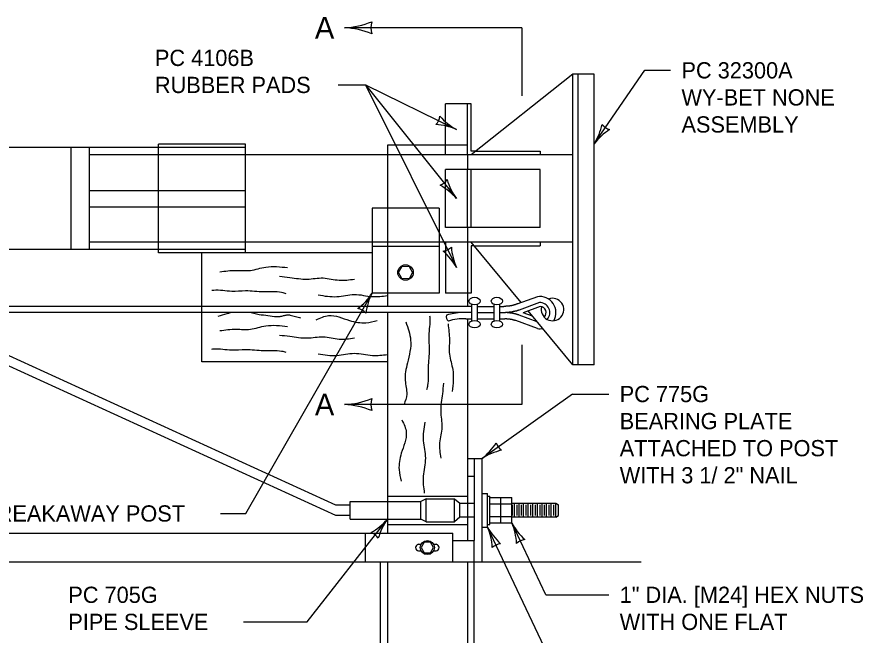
# Model space of a CAD drawing. Extents: x 49991.4 to 50021, y 49987.6 to 50011.4.
# Drawn here: x 50007.796 to 50010.92, y 49991.023 to 49993.307 of the extents above; entities that cross this region are included whole.
import ezdxf

# ---------------------------------------------------------------- set-up
doc = ezdxf.new("R2010")
doc.units = 0
for name, color, linetype in [('Level 1', 7, 'Continuous'), ('Level 2', 7, 'Continuous'), ('Level 3', 7, 'Continuous'), ('Level 4', 7, 'Continuous'), ('Level 6', 7, 'Continuous')]:
    doc.layers.add(name, color=color, linetype=linetype)

msp = doc.modelspace()

# ---------------------------------------------------------------- linework, layer by layer
at = {"layer": 'Level 1'}
for p, q in [((50009.8485, 49993.0962), (50009.4728, 49992.7977)), ((50009.8485, 49992.0223), (50009.8485, 49993.0962)), ((50009.9278, 49993.0962), (50009.8485, 49993.0962)), ((50009.8688, 49992.0223), (50009.8688, 49993.0962)), ((50009.9278, 49992.0223), (50009.9278, 49993.0962)), ((50009.3788, 49992.7977), (50009.3788, 49992.9857)), ((50009.4728, 49992.9857), (50009.3788, 49992.9857)), ((50009.4593, 49992.7977), (50009.4593, 49992.9857)), ((50009.4728, 49992.8112), (50009.4728, 49992.9857)), ((50008.3182, 49992.4355), (50008.3182, 49992.8375)), ((50008.6405, 49992.8375), (50008.3182, 49992.8375)), ((50008.6405, 49992.4355), (50008.6405, 49992.8375)), ((50009.3788, 49992.8334), (50009.1638, 49992.8334)), ((50009.1638, 49992.8334), (50009.1638, 49992.7977)), ((50008.3182, 49992.8247), (50004.6559, 49992.8247)), ((50009.8485, 49992.7977), (50008.6405, 49992.7977)), ((50009.4898, 49992.8112), (50009.4728, 49992.8112)), ((50009.7279, 49992.7437), (50009.3788, 49992.7437)), ((50009.3788, 49992.5294), (50009.3788, 49992.7437)), ((50009.4593, 49992.5294), (50009.4593, 49992.7437)), ((50009.4728, 49992.5294), (50009.4728, 49992.7437)), ((50009.7279, 49992.5294), (50009.7279, 49992.7437)), ((50009.3546, 49992.6008), (50009.1075, 49992.6008)), ((50009.1075, 49992.6008), (50009.1075, 49992.2873)), ((50009.3546, 49992.6008), (50009.3546, 49992.2873)), ((50009.7279, 49992.5294), (50009.3788, 49992.5294)), ((50009.1075, 49992.4753), (50008.6405, 49992.4753)), ((50009.3546, 49992.459), (50009.1075, 49992.459)), ((50009.8485, 49992.4753), (50009.3546, 49992.4753)), ((50009.3788, 49992.4753), (50009.3788, 49992.2873)), ((50009.4593, 49992.4753), (50009.4593, 49992.2379)), ((50009.6579, 49992.2521), (50009.4728, 49992.4753)), ((50009.4728, 49992.4619), (50009.4728, 49992.2873)), ((50009.4839, 49992.4619), (50009.4728, 49992.4619)), ((50008.3182, 49992.4484), (50004.6559, 49992.4484)), ((50008.6405, 49992.4355), (50008.3182, 49992.4355)), ((50009.1075, 49992.4355), (50008.4793, 49992.4355)), ((50008.4793, 49992.0335), (50008.4793, 49992.4355)), ((50009.3546, 49992.2873), (50009.1075, 49992.2873)), ((50009.1638, 49992.2873), (50009.1638, 49992.2379)), ((50009.4728, 49992.2873), (50009.3788, 49992.2873)), ((50009.7178, 49992.2736), (50009.6416, 49992.2463)), ((50009.4754, 49992.2379), (50006.4958, 49992.2379)), ((50009.4754, 49992.184), (50009.4754, 49992.2458)), ((50009.4967, 49992.1839), (50009.4967, 49992.2459)), ((50009.4967, 49992.2379), (50009.5578, 49992.2379)), ((50009.5578, 49992.1839), (50009.5578, 49992.2458)), ((50009.579, 49992.184), (50009.579, 49992.2458)), ((50009.579, 49992.2379), (50009.5943, 49992.2379)), ((50009.7251, 49992.2518), (50009.6501, 49992.2242)), ((50009.7285, 49992.238), (50009.6653, 49992.2145)), ((50008.5847, 49992.215), (50006.4958, 49992.215)), ((50008.9741, 49991.4648), (50007.3336, 49992.215)), ((50008.9741, 49991.5036), (50007.4186, 49992.215)), ((50009.4754, 49992.215), (50008.5847, 49992.215)), ((50009.1638, 49992.215), (50009.1638, 49991.4003)), ((50009.4967, 49992.215), (50009.5578, 49992.215)), ((50009.579, 49992.215), (50009.6005, 49992.215)), ((50009.7169, 49992.1809), (50009.6501, 49992.2057)), ((50009.7, 49992.2013), (50009.6653, 49992.2145)), ((50009.8485, 49992.0223), (50009.6835, 49992.2213)), ((50009.4538, 49992.192), (50009.4754, 49992.192)), ((50009.4593, 49992.192), (50009.4593, 49991.3728)), ((50009.4967, 49992.192), (50009.5578, 49992.192)), ((50009.579, 49992.192), (50009.5976, 49992.192)), ((50009.7185, 49992.156), (50009.6386, 49992.1855)), ((50009.1638, 49992.0335), (50008.4793, 49992.0335)), ((50009.9278, 49992.0223), (50009.8485, 49992.0223)), ((50009.4593, 49991.6758), (50009.5135, 49991.6758)), ((50009.4845, 49991.6758), (50009.4845, 49991.3728)), ((50009.5135, 49991.2942), (50009.5135, 49991.6758)), ((50009.4593, 49991.6101), (50009.4845, 49991.6101)), ((50009.027, 49991.4515), (50009.027, 49991.5169)), ((50009.027, 49991.5169), (50009.1638, 49991.5169)), ((50009.5135, 49991.5468), (50009.5341, 49991.5468)), ((50009.5341, 49991.4226), (50009.5341, 49991.5468)), ((50009.5426, 49991.4326), (50009.5426, 49991.5368)), ((50009.5426, 49991.5313), (50009.6235, 49991.5313)), ((50009.5831, 49991.4381), (50009.5831, 49991.5313)), ((50009.6235, 49991.4381), (50009.6235, 49991.5313)), ((50009.027, 49991.5036), (50008.9741, 49991.5036)), ((50009.4593, 49991.5107), (50009.4845, 49991.5107)), ((50009.5426, 49991.5081), (50009.6235, 49991.5081)), ((50009.6235, 49991.5107), (50009.7861, 49991.5107)), ((50009.6264, 49991.4648), (50009.6264, 49991.5044)), ((50009.6338, 49991.4586), (50009.6338, 49991.5107)), ((50009.6435, 49991.4648), (50009.6435, 49991.5044)), ((50009.6508, 49991.4586), (50009.6508, 49991.5107)), ((50009.6596, 49991.4648), (50009.6596, 49991.5044)), ((50009.6669, 49991.4586), (50009.6669, 49991.5107)), ((50009.677, 49991.4648), (50009.677, 49991.5044)), ((50009.6842, 49991.4586), (50009.6842, 49991.5107)), ((50009.6939, 49991.4648), (50009.6939, 49991.5044)), ((50009.7013, 49991.4586), (50009.7013, 49991.5107)), ((50009.711, 49991.4648), (50009.711, 49991.5044)), ((50009.7185, 49991.4586), (50009.7185, 49991.5107)), ((50009.7281, 49991.4648), (50009.7281, 49991.5044)), ((50009.7354, 49991.4586), (50009.7354, 49991.5107)), ((50009.7446, 49991.4648), (50009.7446, 49991.5044)), ((50009.7518, 49991.4586), (50009.7518, 49991.5107)), ((50009.7616, 49991.4648), (50009.7616, 49991.5044)), ((50009.7691, 49991.4586), (50009.7691, 49991.5107)), ((50009.7788, 49991.4648), (50009.7788, 49991.5044)), ((50009.7861, 49991.4586), (50009.7861, 49991.5107)), ((50009.7861, 49991.5107), (50009.7959, 49991.5044)), ((50009.7959, 49991.4648), (50009.7959, 49991.5044)), ((50009.027, 49991.4648), (50008.9741, 49991.4648)), ((50009.4845, 49991.4586), (50009.4593, 49991.4586)), ((50009.5426, 49991.4612), (50009.6235, 49991.4612)), ((50009.7861, 49991.4586), (50009.6235, 49991.4586)), ((50009.7861, 49991.4586), (50009.7959, 49991.4648)), ((50009.027, 49991.4515), (50009.1638, 49991.4515)), ((50009.5135, 49991.4226), (50009.5341, 49991.4226)), ((50009.5426, 49991.4381), (50009.6235, 49991.4381)), ((50005.1777, 49991.4003), (50009.4058, 49991.4003)), ((50009.0831, 49991.2942), (50009.0831, 49991.4003)), ((50009.4058, 49991.2942), (50009.4058, 49991.4003)), ((50009.4058, 49991.3728), (50009.4845, 49991.3728)), ((50009.4845, 49991.2942), (50009.4845, 49991.3728)), ((50009.2783, 49991.359), (50009.2884, 49991.359)), ((50009.2787, 49991.335), (50009.2884, 49991.335)), ((50009.3345, 49991.335), (50009.3442, 49991.335)), ((50009.3346, 49991.359), (50009.3446, 49991.359)), ((50004.6559, 49991.2942), (50010.1006, 49991.2942))]:
    msp.add_line(p, q, dxfattribs=at)
for points in [[(50009.2183, 49992.386), (50009.244, 49992.3856), (50009.2571, 49992.3631), (50009.2438, 49992.3402), (50009.2177, 49992.3405), (50009.2046, 49992.3633)], [(50009.3231, 49991.327), (50009.3346, 49991.347), (50009.3229, 49991.3671), (50009.2999, 49991.3668), (50009.2885, 49991.3469), (50009.3001, 49991.3268)]]:
    msp.add_lwpolyline(points, close=True, dxfattribs=at)
for points in [[(50009.5341, 49991.5368), (50009.5426, 49991.5368)], [(50009.5341, 49991.4326), (50009.5426, 49991.4326)]]:
    msp.add_lwpolyline(points, dxfattribs=at)
for centre, radius in [((50009.2309, 49992.3631), 0.0287), ((50009.3115, 49991.347), 0.026)]:
    msp.add_circle(centre, radius, dxfattribs=at)
for centre, radius, start, end in [((50009.727, 49992.2149), 0.0595, 329.9229, 98.9717), ((50009.7737, 49992.2262), 0.0415, 164.899, 110.7513), ((50009.727, 49992.2149), 0.037, 317.1104, 92.9441), ((50009.727, 49992.2149), 0.0231, 314.0927, 86.4422), ((50009.3989, 49992.1983), 0.0179, 157.1023, 236.7594), ((50009.4457, 49992.0062), 0.2089, 91.5307, 107.6367), ((50009.4457, 49992.0063), 0.1859, 87.514, 107.7489), ((50009.727, 49992.2149), 0.0595, 261.7086, 279.9748), ((50009.2802, 49991.347), 0.0121, 99.104, 263.011), ((50009.3427, 49991.347), 0.0121, 276.989, 80.896)]:
    msp.add_arc(centre, radius, start, end, dxfattribs=at)
for centre in [(50009.4859, 49992.2577), (50009.5685, 49992.2577), (50009.4859, 49992.172), (50009.5685, 49992.172)]:
    msp.add_ellipse(centre, major_axis=(-0.0209, 0), ratio=0.660302, dxfattribs=at)
for points in [[(50008.5452, 49992.3657), (50008.6054, 49992.371), (50008.6581, 49992.371), (50008.7148, 49992.3833), (50008.7956, 49992.381)], [(50008.7654, 49992.349), (50008.8038, 49992.3449), (50008.8683, 49992.3386), (50008.9272, 49992.3428), (50008.9853, 49992.3347), (50009.042, 49992.3386)], [(50008.5161, 49992.2977), (50008.5228, 49992.2984), (50008.5892, 49992.2944), (50008.6401, 49992.2963), (50008.7068, 49992.2925), (50008.7733, 49992.2903), (50008.7893, 49992.2861)], [(50008.9087, 49992.2804), (50008.9775, 49992.2741), (50009.042, 49992.2821), (50009.1088, 49992.2741), (50009.1638, 49992.2776)], [(50009.644, 49992.2472), (50009.643, 49992.2468), (50009.6421, 49992.2465), (50009.6409, 49992.2462), (50009.64, 49992.2458), (50009.6393, 49992.2455), (50009.6384, 49992.2451), (50009.6374, 49992.2447), (50009.6364, 49992.2444), (50009.6355, 49992.244), (50009.6347, 49992.2437), (50009.6338, 49992.2434), (50009.6328, 49992.2432), (50009.6319, 49992.2429), (50009.631, 49992.2427), (50009.6302, 49992.2424), (50009.6293, 49992.2422), (50009.6282, 49992.242), (50009.6274, 49992.2417), (50009.6267, 49992.2415), (50009.6256, 49992.2412), (50009.6243, 49992.2407), (50009.6235, 49992.2405), (50009.6225, 49992.2403), (50009.6216, 49992.2401), (50009.6206, 49992.2399), (50009.6196, 49992.2398), (50009.6187, 49992.2397), (50009.6177, 49992.2396), (50009.6169, 49992.2396), (50009.6161, 49992.2394), (50009.615, 49992.2393), (50009.6141, 49992.2392), (50009.613, 49992.2391), (50009.6118, 49992.239), (50009.6107, 49992.239), (50009.6099, 49992.2389), (50009.609, 49992.2389), (50009.608, 49992.2388), (50009.6069, 49992.2387), (50009.6063, 49992.2386), (50009.6055, 49992.2384), (50009.6041, 49992.2383), (50009.6032, 49992.2382), (50009.602, 49992.2382), (50009.6009, 49992.2381), (50009.6002, 49992.238), (50009.5994, 49992.2379), (50009.5984, 49992.2379), (50009.5975, 49992.2379), (50009.5966, 49992.2379), (50009.5957, 49992.2379), (50009.5943, 49992.2379)], [(50008.5388, 49992.2021), (50008.5721, 49992.2115), (50008.5847, 49992.215)], [(50008.6604, 49992.215), (50008.6802, 49992.21), (50008.6903, 49992.2083), (50008.7228, 49992.2041), (50008.7553, 49992.2001), (50008.7616, 49992.2), (50008.7679, 49992.2007), (50008.7804, 49992.2037), (50008.793, 49992.2063), (50008.7993, 49992.2066), (50008.8055, 49992.2058), (50008.8247, 49992.201), (50008.8437, 49992.196)], [(50008.9006, 49992.188), (50008.9471, 49992.204), (50009.0239, 49992.1857), (50009.0846, 49992.1775), (50009.1268, 49992.1857)], [(50009.6518, 49992.2248), (50009.6509, 49992.2245), (50009.6501, 49992.2242), (50009.6488, 49992.2237), (50009.6475, 49992.2233), (50009.6466, 49992.223), (50009.6454, 49992.2226), (50009.6443, 49992.2221), (50009.644, 49992.222), (50009.6438, 49992.2218), (50009.6436, 49992.2217), (50009.6433, 49992.2215), (50009.6418, 49992.2211), (50009.6409, 49992.2208), (50009.6401, 49992.2206), (50009.6391, 49992.2203), (50009.6379, 49992.2201), (50009.6371, 49992.2201), (50009.6361, 49992.22), (50009.635, 49992.2197), (50009.634, 49992.2195), (50009.6326, 49992.2192), (50009.6319, 49992.2191), (50009.6315, 49992.2191), (50009.6312, 49992.2191), (50009.6303, 49992.2189), (50009.6293, 49992.2187), (50009.6281, 49992.2185), (50009.627, 49992.2182), (50009.6259, 49992.2178), (50009.6247, 49992.2174), (50009.6237, 49992.2171), (50009.6234, 49992.2171), (50009.6232, 49992.217), (50009.6226, 49992.217), (50009.6213, 49992.2168), (50009.6202, 49992.2167), (50009.6191, 49992.2167), (50009.6182, 49992.2167), (50009.6172, 49992.2166), (50009.6159, 49992.2164), (50009.6149, 49992.2162), (50009.614, 49992.2161), (50009.6128, 49992.2159), (50009.6117, 49992.2158), (50009.6105, 49992.2156), (50009.6102, 49992.2156), (50009.6099, 49992.2155), (50009.6097, 49992.2154), (50009.6094, 49992.2154), (50009.609, 49992.2154), (50009.6087, 49992.2154), (50009.6079, 49992.2154), (50009.6071, 49992.2153), (50009.6059, 49992.2151), (50009.6045, 49992.215), (50009.604, 49992.215), (50009.6022, 49992.215), (50009.6012, 49992.215), (50009.6005, 49992.215)], [(50009.651, 49992.2054), (50009.6506, 49992.2055), (50009.6501, 49992.2057), (50009.6487, 49992.2062), (50009.6476, 49992.2065), (50009.6468, 49992.2067), (50009.6453, 49992.2071), (50009.6445, 49992.2074), (50009.6431, 49992.2079), (50009.6421, 49992.2083), (50009.6413, 49992.2085), (50009.6401, 49992.2088), (50009.6387, 49992.2092), (50009.6377, 49992.2095), (50009.6367, 49992.2098), (50009.6358, 49992.21), (50009.6347, 49992.2103), (50009.6336, 49992.2105), (50009.6325, 49992.2108), (50009.6321, 49992.2108), (50009.6318, 49992.2108), (50009.6315, 49992.2109), (50009.6312, 49992.2109), (50009.6301, 49992.2112), (50009.6292, 49992.2114), (50009.6279, 49992.2118), (50009.6276, 49992.2118), (50009.6274, 49992.2119), (50009.6271, 49992.212), (50009.6269, 49992.2121), (50009.626, 49992.2123), (50009.6247, 49992.2126), (50009.6238, 49992.2127), (50009.6234, 49992.2128), (50009.6231, 49992.2129), (50009.6228, 49992.213), (50009.6225, 49992.213), (50009.6215, 49992.2131), (50009.6204, 49992.2132), (50009.6189, 49992.2133), (50009.6178, 49992.2133), (50009.617, 49992.2134), (50009.6157, 49992.2135), (50009.6145, 49992.2136), (50009.6134, 49992.2137), (50009.6123, 49992.2139), (50009.6113, 49992.214), (50009.6102, 49992.2141), (50009.6089, 49992.2144), (50009.6086, 49992.2144), (50009.6083, 49992.2144), (50009.6079, 49992.2145), (50009.6076, 49992.2145), (50009.6068, 49992.2147), (50009.6056, 49992.2148), (50009.6053, 49992.2148), (50009.605, 49992.2149), (50009.6044, 49992.215), (50009.604, 49992.215), (50009.6022, 49992.215), (50009.6012, 49992.215), (50009.6005, 49992.215)], [(50009.2317, 49992.1803), (50009.2499, 49992.1137), (50009.2379, 49992.0288), (50009.2297, 49991.9638), (50009.2354, 49991.9136), (50009.2256, 49991.8754)], [(50009.3198, 49992.203), (50009.3205, 49992.1963), (50009.3165, 49992.1299), (50009.3184, 49992.079), (50009.3146, 49992.0123), (50009.3124, 49991.9458), (50009.3082, 49991.9298)], [(50009.3878, 49992.1739), (50009.3931, 49992.1137), (50009.3931, 49992.061), (50009.4054, 49992.0043), (50009.4031, 49991.9235)], [(50009.6386, 49992.1855), (50009.6377, 49992.1857), (50009.6365, 49992.1859), (50009.6357, 49992.186), (50009.6348, 49992.1861), (50009.634, 49992.1863), (50009.6331, 49992.1865), (50009.6321, 49992.1867), (50009.6309, 49992.1869), (50009.63, 49992.1872), (50009.6293, 49992.1874), (50009.628, 49992.1879), (50009.6272, 49992.1881), (50009.6266, 49992.1883), (50009.6256, 49992.1886), (50009.6252, 49992.1886), (50009.6249, 49992.1887), (50009.6246, 49992.1887), (50009.6242, 49992.1888), (50009.624, 49992.1889), (50009.6238, 49992.189), (50009.6236, 49992.189), (50009.6234, 49992.1891), (50009.6225, 49992.1893), (50009.6218, 49992.1895), (50009.6206, 49992.1897), (50009.6195, 49992.19), (50009.6192, 49992.19), (50009.619, 49992.19), (50009.6184, 49992.19), (50009.6177, 49992.19), (50009.6169, 49992.1901), (50009.6156, 49992.1902), (50009.6149, 49992.1903), (50009.6141, 49992.1903), (50009.6131, 49992.1905), (50009.6126, 49992.1905), (50009.6123, 49992.1905), (50009.6121, 49992.1905), (50009.6108, 49992.1906), (50009.61, 49992.1907), (50009.6097, 49992.1907), (50009.6095, 49992.1907), (50009.6093, 49992.1907), (50009.609, 49992.1908), (50009.6082, 49992.1909), (50009.6072, 49992.191), (50009.6064, 49992.1911), (50009.6053, 49992.1913), (50009.6044, 49992.1914), (50009.6036, 49992.1915), (50009.6026, 49992.1917), (50009.6016, 49992.1917), (50009.6006, 49992.1918), (50009.5996, 49992.1918), (50009.5987, 49992.192), (50009.5976, 49992.192)], [(50008.5452, 49992.1483), (50008.6054, 49992.1536), (50008.6581, 49992.1536), (50008.7148, 49992.1659), (50008.7956, 49992.1636)], [(50008.7654, 49992.1316), (50008.8038, 49992.1275), (50008.8683, 49992.1212), (50008.9272, 49992.1254), (50008.9853, 49992.1173), (50009.042, 49992.1212)], [(50008.5161, 49992.0803), (50008.5228, 49992.081), (50008.5892, 49992.077), (50008.6401, 49992.0789), (50008.7068, 49992.0751), (50008.7733, 49992.0729), (50008.7893, 49992.0687)], [(50008.9087, 49992.063), (50008.9775, 49992.0567), (50009.042, 49992.0647), (50009.1088, 49992.0567), (50009.1638, 49992.0602)], [(50009.3711, 49991.9537), (50009.367, 49991.9153), (50009.3607, 49991.8508), (50009.3649, 49991.7919), (50009.3568, 49991.7338), (50009.3607, 49991.6771)], [(50009.2176, 49991.8185), (50009.2336, 49991.772), (50009.2153, 49991.6952), (50009.2071, 49991.6345), (50009.2153, 49991.5923)], [(50009.3025, 49991.8104), (50009.2962, 49991.7416), (50009.3042, 49991.6771), (50009.2962, 49991.6103), (50009.3002, 49991.5476)]]:
    msp.add_spline(points, degree=3, dxfattribs=at)
at = {"layer": 'Level 3'}
for p, q in [((50009.9278, 49992.8382), (50010.1145, 49993.1101)), ((50008.9824, 49993.0561), (50009.0836, 49993.0561)), ((50009.0836, 49993.0561), (50009.4191, 49992.8917)), ((50009.0836, 49993.0561), (50009.4191, 49992.6365)), ((50009.0836, 49993.0561), (50009.4191, 49992.3813)), ((50008.6417, 49991.4728), (50009.1075, 49992.2873)), ((50008.5482, 49991.4728), (50008.6417, 49991.4728))]:
    msp.add_line(p, q, dxfattribs=at)
for points in [[(50010.1145, 49993.1101), (50010.2099, 49993.1101)], [(50009.8474, 49991.9141), (50009.5135, 49991.6758)], [(50009.8474, 49991.9141), (50009.9818, 49991.9141)], [(50008.8674, 49991.0723), (50009.1638, 49991.4515)], [(50009.8418, 49990.7723), (50009.5341, 49991.4226)], [(50009.7493, 49991.1723), (50009.6235, 49991.4381)], [(50009.7493, 49991.1723), (50009.9818, 49991.1723)], [(50008.6326, 49991.0723), (50008.8674, 49991.0723)]]:
    msp.add_lwpolyline(points, dxfattribs=at)
for centre, radius, start, end in [((50008.9898, 49993.5777), 0.3107, 272.8273, 292.0772), ((50008.9929, 49992.9712), 0.2964, 67.456, 87.6395), ((50009.1761, 49993.2674), 0.073, 162.1388, 197.8612), ((50009.3039, 49992.9481), 0.0548, 316.0333, 351.7556), ((50009.525, 49993.0871), 0.2223, 221.3505, 241.534), ((50009.327, 49992.6777), 0.233, 66.7218, 85.9716), ((50009.7294, 49992.9605), 0.233, 328.3519, 347.6017), ((50010.1057, 49992.7049), 0.2223, 122.9806, 143.1641), ((50010.0003, 49992.9439), 0.0548, 217.6634, 253.3858), ((50009.339, 49992.7366), 0.0548, 290.7836, 326.506), ((50009.5983, 49992.7681), 0.2223, 196.1008, 216.2843), ((50009.2445, 49992.4822), 0.233, 41.4721, 60.722), ((50009.362, 49992.4961), 0.0548, 278.5747, 314.297), ((50009.6221, 49992.472), 0.2223, 183.8919, 204.0754), ((50009.2158, 49992.2674), 0.233, 29.2632, 48.513), ((50008.9192, 49992.4055), 0.2223, 307.6919, 327.8754), ((50009.3152, 49992.1818), 0.233, 153.0632, 172.313), ((50009.0438, 49992.176), 0.0548, 42.3747, 78.097), ((50008.9898, 49992.1855), 0.3107, 272.8273, 292.0772), ((50009.1761, 49991.8752), 0.073, 162.1388, 197.8612), ((50008.9929, 49991.579), 0.2964, 67.456, 87.6395), ((50009.3689, 49991.8585), 0.233, 308.3423, 327.5921), ((50009.6351, 49991.4897), 0.2223, 102.971, 123.1545), ((50009.6178, 49991.7503), 0.0548, 197.6538, 233.3761), ((50008.9944, 49991.5955), 0.2223, 299.4417, 319.6252), ((50009.3542, 49991.3172), 0.233, 144.813, 164.0629), ((50009.3294, 49991.3359), 0.2223, 2.7779, 22.9614), ((50009.7395, 49991.5325), 0.233, 208.1492, 227.3991), ((50009.4188, 49991.3513), 0.2223, 2.7837, 22.9672), ((50009.8289, 49991.548), 0.233, 208.155, 227.4048), ((50009.0848, 49991.3505), 0.0548, 34.1245, 69.8469), ((50009.5889, 49991.3067), 0.0548, 97.4608, 133.1831), ((50009.6783, 49991.3222), 0.0548, 97.4665, 133.1888)]:
    msp.add_arc(centre, radius, start, end, dxfattribs=at)
at = {"layer": 'Level 4'}
for p, q in [((50009.4593, 49992.8334), (50009.3788, 49992.8334)), ((50007.996, 49992.4484), (50007.996, 49992.8247)), ((50008.0639, 49992.4484), (50008.0639, 49992.8247)), ((50008.6405, 49992.7977), (50008.0639, 49992.7977)), ((50008.6405, 49992.8247), (50008.3182, 49992.8247)), ((50009.1638, 49992.7977), (50009.1638, 49992.2873)), ((50009.4593, 49992.7977), (50009.4593, 49992.7437)), ((50009.4898, 49992.8112), (50009.7279, 49992.8112)), ((50009.7279, 49992.8112), (50009.7279, 49992.7977)), ((50008.6405, 49992.6647), (50008.0639, 49992.6647)), ((50008.6405, 49992.6043), (50008.0639, 49992.6043)), ((50009.4593, 49992.5294), (50009.4593, 49992.4753)), ((50008.6405, 49992.4753), (50008.0639, 49992.4753)), ((50009.3546, 49992.4753), (50009.1075, 49992.4753)), ((50009.4839, 49992.4619), (50009.7279, 49992.4619)), ((50009.7279, 49992.4753), (50009.7279, 49992.4619)), ((50008.6405, 49992.4484), (50008.3182, 49992.4484)), ((50009.1638, 49991.5363), (50009.4593, 49991.5363)), ((50009.1638, 49991.5169), (50009.2878, 49991.5169)), ((50009.3073, 49991.5269), (50009.2878, 49991.5169)), ((50009.2878, 49991.4515), (50009.2878, 49991.5169)), ((50009.3073, 49991.5269), (50009.4116, 49991.5269)), ((50009.3073, 49991.4423), (50009.3073, 49991.5269)), ((50009.4116, 49991.5269), (50009.431, 49991.5107)), ((50009.4116, 49991.4423), (50009.4116, 49991.5269)), ((50009.431, 49991.4586), (50009.431, 49991.5107)), ((50009.431, 49991.5107), (50009.4593, 49991.5107)), ((50009.431, 49991.4586), (50009.4116, 49991.4423)), ((50009.4593, 49991.4586), (50009.431, 49991.4586)), ((50009.1638, 49991.4515), (50009.2878, 49991.4515)), ((50009.1638, 49991.432), (50009.4593, 49991.432)), ((50009.3073, 49991.4423), (50009.2878, 49991.4515)), ((50009.3073, 49991.4423), (50009.4116, 49991.4423)), ((50009.1384, 49989.7086), (50009.1384, 49991.2942)), ((50009.1638, 49991.2942), (50009.1638, 49990.5512)), ((50009.4593, 49991.2942), (50009.4593, 49990.5512)), ((50009.4845, 49989.7086), (50009.4845, 49991.2942))]:
    msp.add_line(p, q, dxfattribs=at)
at = {"layer": 'Level 6'}
for p, q in [((50009.6607, 49993.2674), (50009.0051, 49993.2674)), ((50009.6607, 49993.2674), (50009.6607, 49993.0164)), ((50009.6607, 49992.0962), (50009.6607, 49991.8752)), ((50009.6607, 49991.8752), (50009.0051, 49991.8752))]:
    msp.add_line(p, q, dxfattribs=at)

# ---------------------------------------------------------------- texts
at = {"layer": 'Level 2'}
for s, height, p in [('A', 0.08, (50008.8964, 49993.2274)), ('PC 4106B', 0.06, (50008.3055, 49993.1261)), ('PC 32300A', 0.06, (50010.2499, 49993.0801)), ('RUBBER PADS', 0.06, (50008.3055, 49993.0261)), ('WY-BET NONE', 0.06, (50010.2499, 49992.9801)), ('ASSEMBLY', 0.06, (50010.2499, 49992.8801)), ('PC 775G', 0.06, (50010.0218, 49991.8841)), ('A', 0.08, (50008.8964, 49991.8352)), ('BEARING PLATE', 0.06, (50010.0218, 49991.7841)), ('ATTACHED TO POST', 0.06, (50010.0218, 49991.6841)), ('WITH 3 1/ 2" NAIL', 0.06, (50010.0218, 49991.5841)), ('PLATE BREAKAWAY POST', 0.06, (50007.3913, 49991.4428)), ('1" DIA. [M24] HEX NUTS', 0.06, (50010.0218, 49991.1423)), ('PC 705G', 0.06, (50007.9858, 49991.1423)), ('PIPE SLEEVE', 0.06, (50007.9858, 49991.0423)), ('WITH ONE FLAT', 0.06, (50010.0218, 49991.0423))]:
    msp.add_text(s, height=height, dxfattribs=at).set_placement(p)

doc.saveas('drawing.dxf')
